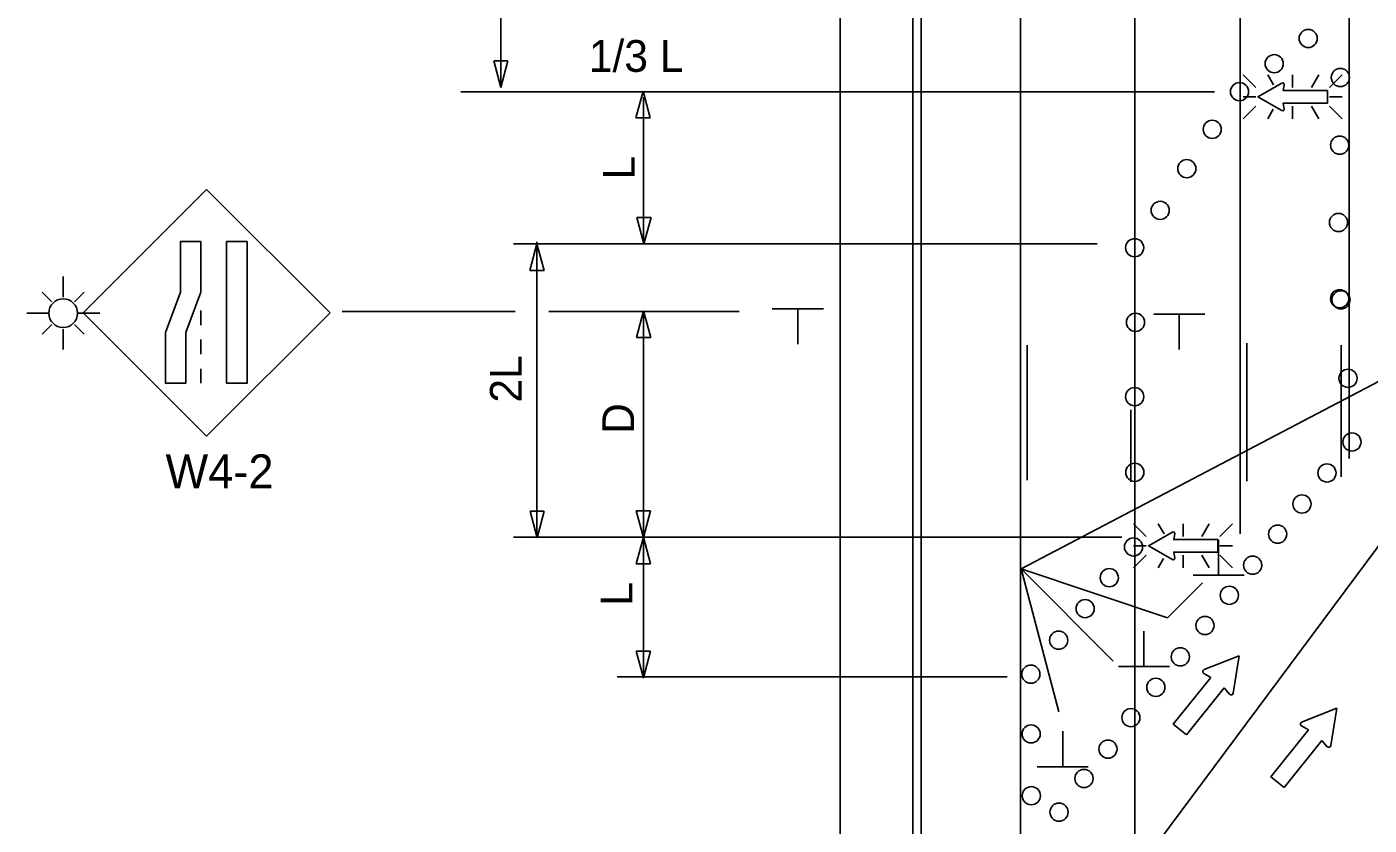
# Model space of a CAD drawing. Extents: x 16038 to 19504, y 5920 to 8321.
# Drawn here: x 16791.3 to 17086.7, y 7704.1 to 7879.9 of the extents above; entities that cross this region are included whole.
import ezdxf

# ---------------------------------------------------------------- set-up
doc = ezdxf.new("R2010")
doc.units = 0
for name, color, linetype in [('ALI_LEGAL_EX', 7, 'Continuous'), ('MT_SCRATCH_LEVEL_E', 7, 'Continuous'), ('PAVT_EDGE_EX', 7, 'Continuous'), ('TRAFFIC_SIGNS_PR', 7, 'Continuous'), ('TYPICAL_TEXT_DIMEN_PR', 7, 'Continuous')]:
    doc.layers.add(name, color=color, linetype=linetype)

msp = doc.modelspace()

# ---------------------------------------------------------------- linework, layer by layer
at = {"layer": 'ALI_LEGAL_EX'}
for points in [[(17011.47, 7780.07), (17011.47, 7809.78)], [(17059.83, 7779.87), (17059.83, 7810.22)], [(17080.54, 7780.8), (17080.54, 7809.77)], [(17034.28, 7779.7), (17034.28, 7795.59)]]:
    msp.add_lwpolyline(points, dxfattribs=at)
at = {"layer": 'MT_SCRATCH_LEVEL_E'}
for p, q in [((17050.38, 7738.39), (17058.15, 7741.43)), ((17050.38, 7738.39), (17058.15, 7741.43)), ((17058.15, 7741.43), (17056.81, 7733.21)), ((17058.15, 7741.43), (17056.81, 7733.21)), ((17051.91, 7736.68), (17050.33, 7737.55)), ((17051.91, 7736.68), (17050.33, 7737.55)), ((17043.6, 7726.36), (17051.91, 7736.68)), ((17043.6, 7726.36), (17051.91, 7736.68)), ((17054.82, 7734.34), (17046.51, 7724.01)), ((17054.82, 7734.34), (17046.51, 7724.01)), ((17056.01, 7732.98), (17054.82, 7734.34)), ((17056.01, 7732.98), (17054.82, 7734.34)), ((17071.87, 7726.83), (17079.64, 7729.87)), ((17071.87, 7726.83), (17079.64, 7729.87)), ((17079.64, 7729.87), (17078.3, 7721.65)), ((17079.64, 7729.87), (17078.3, 7721.65)), ((17046.51, 7724.01), (17043.6, 7726.36)), ((17046.51, 7724.01), (17043.6, 7726.36)), ((17065.08, 7714.8), (17073.4, 7725.12)), ((17065.08, 7714.8), (17073.4, 7725.12)), ((17073.4, 7725.12), (17071.81, 7725.99)), ((17073.4, 7725.12), (17071.81, 7725.99)), ((17076.31, 7722.78), (17068, 7712.45)), ((17076.31, 7722.78), (17068, 7712.45)), ((17077.5, 7721.42), (17076.31, 7722.78)), ((17077.5, 7721.42), (17076.31, 7722.78)), ((17068, 7712.45), (17065.08, 7714.8)), ((17068, 7712.45), (17065.08, 7714.8))]:
    msp.add_line(p, q, dxfattribs=at)
for centre, start, end in [((17050.56, 7737.95), 111.3861, 241.123), ((17050.56, 7737.95), 111.3861, 241.123), ((17056.36, 7733.29), 221.1954, 350.7344), ((17056.36, 7733.29), 221.1954, 350.7344), ((17072.05, 7726.4), 111.3861, 241.123), ((17072.05, 7726.4), 111.3861, 241.123), ((17077.84, 7721.73), 221.1954, 350.7344), ((17077.84, 7721.73), 221.1954, 350.7344)]:
    msp.add_arc(centre, 0.463, start, end, dxfattribs=at)
at = {"layer": 'PAVT_EDGE_EX'}
for p, q in [((16970.3, 8210.68), (16970.3, 7367.79)), ((16986.3, 8210.68), (16986.3, 7368.22)), ((17058.3, 8211.6), (17058.3, 7768.24)), ((17082.3, 8210.68), (17082.3, 7784.85)), ((17035.15, 8180.7), (17035.15, 7351.51)), ((16988.15, 8162.34), (16988.15, 7333.15)), ((17010.01, 8162.15), (17010.01, 7332.97)), ((17058.3, 8068.76), (17058.3, 7795.75)), ((17082.3, 8068.76), (17082.3, 7826.61))]:
    msp.add_line(p, q, dxfattribs=at)
at = {"layer": 'TRAFFIC_SIGNS_PR'}
for p, q in [((17058.97, 7869.32), (17061.78, 7866.5)), ((17065.69, 7867.13), (17064.43, 7869.32)), ((17069.87, 7866.5), (17069.87, 7869.32)), ((17074.01, 7866.5), (17075.63, 7869.32)), ((17077.96, 7866.5), (17080.78, 7869.32)), ((17061.78, 7864.47), (17058.97, 7864.47)), ((17077.96, 7864.47), (17080.78, 7864.47)), ((17058.97, 7859.62), (17061.78, 7862.44)), ((17064.4, 7859.61), (17065.61, 7861.71)), ((17069.87, 7862.44), (17069.87, 7859.61)), ((17075.66, 7859.61), (17074.03, 7862.44)), ((17077.96, 7862.44), (17080.78, 7859.61)), ((16830.88, 7844.07), (16803.72, 7816.91)), ((16858.03, 7816.91), (16830.88, 7844.07)), ((17162.88, 7840.66), (17010.11, 7760.54)), ((16799.3, 7820.4), (16799.3, 7824.9)), ((16796.79, 7819.35), (16794.68, 7821.46)), ((16801.81, 7819.35), (16803.92, 7821.46)), ((16796.15, 7816.84), (16791.31, 7816.84)), ((16802.45, 7816.84), (16807.34, 7816.84)), ((16803.72, 7816.91), (16830.88, 7789.76)), ((16829.63, 7817.41), (16829.63, 7814.21)), ((16830.88, 7789.76), (16858.03, 7816.91)), ((16796.79, 7814.33), (16794.68, 7812.22)), ((16801.81, 7814.33), (16803.92, 7812.22)), ((16799.3, 7808.87), (16799.3, 7813.29)), ((16829.63, 7811.01), (16829.63, 7807.81)), ((16829.63, 7804.61), (16829.63, 7801.41)), ((17034.86, 7770.48), (17037.68, 7767.66)), ((17041.58, 7768.3), (17040.32, 7770.49)), ((17045.76, 7767.66), (17045.76, 7770.49)), ((17049.9, 7767.66), (17051.53, 7770.49)), ((17053.85, 7767.66), (17056.67, 7770.49)), ((17037.68, 7765.63), (17034.86, 7765.63)), ((17034.86, 7760.78), (17037.68, 7763.6)), ((17045.76, 7763.6), (17045.76, 7760.78)), ((17051.55, 7760.78), (17049.92, 7763.6)), ((17053.85, 7765.63), (17056.67, 7765.63)), ((17053.85, 7763.6), (17056.67, 7760.78)), ((17040.3, 7760.78), (17041.5, 7762.87))]:
    msp.add_line(p, q, dxfattribs=at)
for points in [[(17067.54, 7867.48), (17062.23, 7864.47), (17067.54, 7861.43)], [(17068.04, 7861.78), (17067.81, 7863.08), (17077.54, 7863.08), (17077.54, 7865.82), (17067.81, 7865.82), (17068.05, 7867.13)], [(17043.44, 7768.65), (17038.13, 7765.63), (17043.44, 7762.59)], [(17043.94, 7762.95), (17043.71, 7764.25), (17053.43, 7764.25), (17053.43, 7766.99), (17043.71, 7766.99), (17043.94, 7768.29)]]:
    msp.add_lwpolyline(points, dxfattribs=at)
for points in [[(16829.63, 7832.65), (16829.63, 7821.47), (16826.29, 7812.59), (16826.29, 7801.41), (16821.79, 7801.41), (16821.79, 7812.59), (16825.14, 7821.47), (16825.14, 7832.65)], [(16839.77, 7832.65), (16839.77, 7801.41), (16835.27, 7801.41), (16835.27, 7832.65)]]:
    msp.add_lwpolyline(points, close=True, dxfattribs=at)
for centre, radius in [((17073.31, 7877.31), 2), ((17065.83, 7871.75), 2), ((17080.39, 7868.72), 2), ((17058.2, 7865.59), 2), ((17052.19, 7857.3), 2), ((17080.24, 7853.82), 2), ((17046.59, 7848.65), 2), ((17040.74, 7839.46), 2), ((17079.98, 7836.8), 2), ((17035.1, 7831.24), 2), ((16799.3, 7816.84), 3.15), ((17080.24, 7820.02), 2), ((17080.51, 7819.78), 2), ((17035.3, 7814.82), 2), ((17082.08, 7802.51), 2), ((17035.12, 7798.46), 2), ((17082.93, 7788.5), 2), ((17082.93, 7788.5), 2), ((17035.14, 7781.8), 2), ((17077.43, 7781.67), 2), ((17071.93, 7774.84), 2), ((17066.58, 7768.2), 2), ((17034.87, 7765.39), 2), ((17029.53, 7758.62), 2), ((17061.08, 7761.37), 2), ((17055.96, 7754.75), 2), ((17024.21, 7751.81), 2), ((17050.58, 7748.09), 2), ((17018.39, 7744.86), 2), ((17045.16, 7741.19), 2), ((17012.27, 7737.38), 2), ((17039.77, 7734.49), 2), ((17034.29, 7727.82), 2), ((17012.33, 7724.23), 2), ((17029.24, 7720.88), 2), ((17023.96, 7714.42), 2), ((17012.37, 7710.62), 2), ((17018.48, 7707.01), 2)]:
    msp.add_circle(centre, radius, dxfattribs=at)
for centre, start, end in [((17067.71, 7867.18), 350.7308, 118.8916), ((17067.71, 7861.72), 241.4833, 9.9593), ((17043.6, 7768.35), 350.7308, 118.8916), ((17043.6, 7762.89), 241.4833, 9.9593)]:
    msp.add_arc(centre, 0.341, start, end, dxfattribs=at)
at = {"layer": 'TYPICAL_TEXT_DIMEN_PR'}
for p, q in [((16895.62, 7866.51), (16895.62, 7916.51)), ((16895.62, 7866.51), (16894.05, 7872.37)), ((16894.05, 7872.37), (16895.62, 7872.37)), ((16895.62, 7872.37), (16897.19, 7872.37)), ((16897.19, 7872.37), (16895.62, 7866.51)), ((17052.68, 7865.59), (16886.81, 7865.59)), ((16925.37, 7859.84), (16926.94, 7865.7)), ((16926.94, 7865.7), (16928.51, 7859.84)), ((16926.99, 7832.57), (16926.99, 7864.42)), ((16926.94, 7859.84), (16925.37, 7859.84)), ((16928.51, 7859.84), (16926.94, 7859.84)), ((16927.11, 7832.07), (16925.54, 7837.93)), ((16925.54, 7837.93), (16927.11, 7837.93)), ((16927.11, 7837.93), (16928.68, 7837.93)), ((16928.68, 7837.93), (16927.11, 7832.07)), ((17026.83, 7832.14), (16898.39, 7832.14)), ((16902, 7826.26), (16903.57, 7832.12)), ((16903.57, 7832.12), (16905.14, 7826.26)), ((16903.58, 7767.65), (16903.58, 7832.57)), ((16903.57, 7826.26), (16902, 7826.26)), ((16905.14, 7826.26), (16903.57, 7826.26)), ((16898.8, 7817.21), (16860.7, 7817.21)), ((16948.09, 7817.21), (16906.18, 7817.21)), ((16925.48, 7811.47), (16927.05, 7817.34)), ((16926.99, 7767.54), (16926.99, 7816.97)), ((16927.05, 7817.34), (16928.62, 7811.47)), ((16955.37, 7817.78), (16966.62, 7817.78)), ((16960.99, 7817.78), (16960.99, 7809.99)), ((17039.31, 7816.61), (17050.56, 7816.61)), ((17044.93, 7816.61), (17044.93, 7808.82)), ((16927.05, 7811.47), (16925.48, 7811.47)), ((16928.62, 7811.47), (16927.05, 7811.47)), ((17036.11, 7694.87), (17105.73, 7788.44)), ((16903.62, 7767.41), (16902.05, 7773.27)), ((16902.05, 7773.27), (16903.62, 7773.27)), ((16903.62, 7773.27), (16905.19, 7773.27)), ((16905.19, 7773.27), (16903.62, 7767.41)), ((16926.99, 7767.49), (16925.42, 7773.36)), ((16925.42, 7773.36), (16926.99, 7773.36)), ((16926.99, 7773.36), (16928.56, 7773.36)), ((16928.56, 7773.36), (16926.99, 7767.49)), ((16898.39, 7767.5), (17032.31, 7767.5)), ((16925.42, 7761.66), (16926.99, 7767.52)), ((16926.99, 7767.52), (16928.56, 7761.66)), ((16926.99, 7736.51), (16926.99, 7767.43)), ((17053.6, 7759.17), (17053.6, 7766.95)), ((16926.99, 7761.66), (16925.42, 7761.66)), ((16928.56, 7761.66), (16926.99, 7761.66)), ((17018.4, 7729.12), (17010.11, 7760.54)), ((17010.11, 7760.54), (17030.37, 7740.21)), ((17042.35, 7749.76), (17010.11, 7760.54)), ((17059.23, 7759.17), (17047.98, 7759.17)), ((17050.02, 7757.46), (17042.35, 7749.76)), ((17037.15, 7739.06), (17037.15, 7746.85)), ((16926.99, 7736.57), (16925.42, 7742.43)), ((16925.42, 7742.43), (16926.99, 7742.43)), ((16926.99, 7742.43), (16928.56, 7742.43)), ((16928.56, 7742.43), (16926.99, 7736.57)), ((17042.78, 7739.06), (17031.53, 7739.06)), ((16921.24, 7736.83), (17007.08, 7736.83)), ((17019.29, 7717.01), (17019.29, 7724.8)), ((17024.91, 7717.01), (17013.66, 7717.01))]:
    msp.add_line(p, q, dxfattribs=at)

# ---------------------------------------------------------------- texts
at = {"layer": 'TRAFFIC_SIGNS_PR'}
msp.add_text('W4-2', height=7.44, dxfattribs=at).set_placement((16821.83, 7778.32))
at = {"layer": 'TYPICAL_TEXT_DIMEN_PR'}
msp.add_text('1/3 L', height=7, dxfattribs=at).set_placement((16914.99, 7869.96))
msp.add_text('1/3 L', height=7, dxfattribs=at).set_placement((16914.99, 7869.96))
for s, p in [('L', (16925.11, 7846.28)), ('2L', (16900.23, 7797.15)), ('D', (16924.96, 7790.26)), ('L', (16924.58, 7752.45))]:
    msp.add_text(s, height=7, rotation=90, dxfattribs=at).set_placement(p)

doc.saveas('drawing.dxf')
